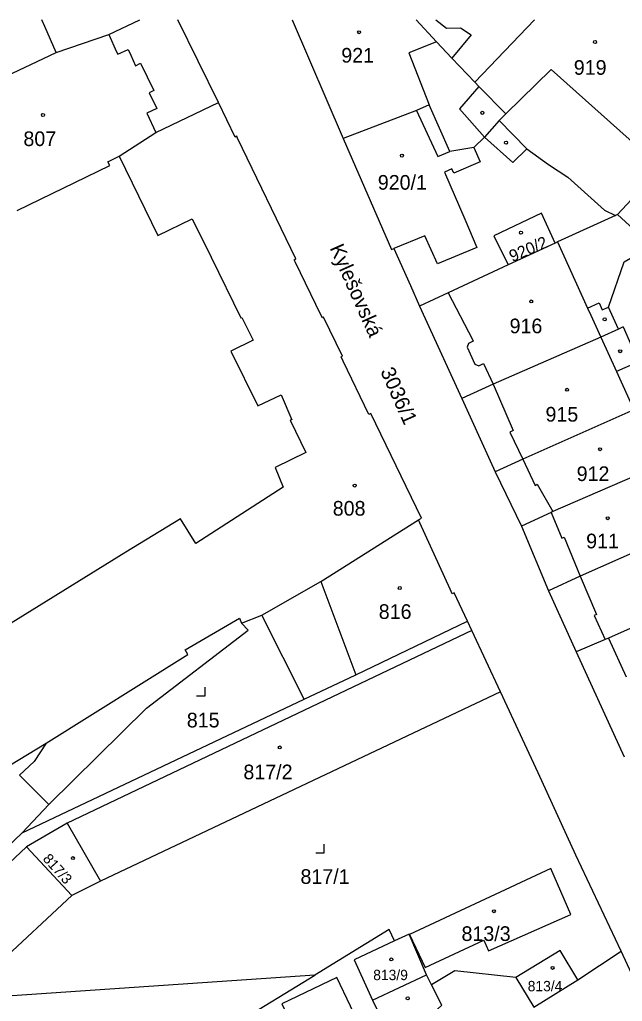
# Model space of a CAD drawing. Extents: x -496682 to -495907, y -1088575 to -1088018.
# Drawn here: x -496321.7 to -496251.9, y -1088133.3 to -1088019.5 of the extents above; entities that cross this region are included whole.
import ezdxf

# ---------------------------------------------------------------- set-up
doc = ezdxf.new("R2010")
doc.units = 0
for name, color, linetype in [('Hranice parcel', 7, 'Continuous'), ('Parcelní čísla', 7, 'Continuous'), ('Pop  PČ popisy', 7, 'Continuous'), ('Vnitřní kresba', 7, 'Continuous'), ('Značky budov', 7, 'Continuous'), ('Značky kultur', 7, 'Continuous')]:
    doc.layers.add(name, color=color, linetype=linetype)

msp = doc.modelspace()

# ---------------------------------------------------------------- linework, layer by layer
at = {"layer": 'Hranice parcel'}
for p, q in [((-496298.65, -1088029.08), (-496303.35, -1088019.49)), ((-496290.12, -1088019.49), (-496284.21, -1088033.27)), ((-496268.93, -1088026.74), (-496262.02, -1088019.49)), ((-496252.41, -1088042.06), (-496252.65, -1088042.17)), ((-496259.65, -1088045.38), (-496265.09, -1088047.92)), ((-496275.35, -1088052.7), (-496270.45, -1088063.42)), ((-496251.78, -1088055.1), (-496252.31, -1088055.35)), ((-496270.45, -1088063.42), (-496266.61, -1088071.89)), ((-496266.61, -1088071.89), (-496263.53, -1088078.19)), ((-496263.53, -1088078.19), (-496260.43, -1088085.68)), ((-496260.43, -1088085.68), (-496257.2, -1088092.78)), ((-496288.72, -1088098.27), (-496293.61, -1088088.52)), ((-496269.29, -1088090.31), (-496269.79, -1088089.23)), ((-496269.29, -1088090.31), (-496316.2, -1088112.62)), ((-496265.99, -1088097.42), (-496269.29, -1088090.31)), ((-496257.2, -1088092.78), (-496251.66, -1088104.94)), ((-496265.99, -1088097.42), (-496312.31, -1088119.35)), ((-496321.41, -1088113.75), (-496288.72, -1088098.27)), ((-496321.41, -1088113.75), (-496318.3, -1088110.48)), ((-496316.2, -1088112.62), (-496320.9, -1088115.37)), ((-496316.2, -1088112.62), (-496312.31, -1088119.35)), ((-496373.06, -1088163.12), (-496321.41, -1088113.75)), ((-496320.9, -1088115.37), (-496333.69, -1088127.43)), ((-496315.65, -1088120.99), (-496320.9, -1088115.37)), ((-496312.31, -1088119.35), (-496315.65, -1088120.99)), ((-496328.55, -1088133.03), (-496315.65, -1088120.99)), ((-496257, -1088130.8), (-496251.99, -1088127.48)), ((-496247.14, -1088138.02), (-496251.99, -1088127.48)), ((-496287.5, -1088130.23), (-496328.55, -1088133.03)), ((-496299.6, -1088137.62), (-496287.5, -1088130.23)), ((-496280.81, -1088133.14), (-496274.56, -1088130.21)), ((-496273.98, -1088131.36), (-496274.56, -1088130.21)), ((-496264.2, -1088130.52), (-496262.1, -1088133.95)), ((-496262.1, -1088133.95), (-496257, -1088130.8))]:
    msp.add_line(p, q, dxfattribs=at)
for points in [[(-496324.74, -1088026.75), (-496317.45, -1088023.28), (-496311.34, -1088021.2), (-496307.78, -1088019.49)], [(-496275.76, -1088019.49), (-496273.38, -1088022.04), (-496271.62, -1088023.96), (-496268.93, -1088026.74)], [(-496268.93, -1088026.74), (-496268.47, -1088027.22), (-496265.37, -1088030.41), (-496266.13, -1088031.18)], [(-496238.61, -1088027.35), (-496247.36, -1088036.67), (-496247.58, -1088036.9), (-496252.41, -1088042.06)], [(-496310.17, -1088035.32), (-496305.9, -1088032.56), (-496298.65, -1088029.08)], [(-496275.49, -1088077.48), (-496275.13, -1088077.26), (-496281.01, -1088065.15), (-496281.24, -1088065.26), (-496284.2, -1088059.06), (-496284.42, -1088058.56), (-496284.28, -1088058.49), (-496286.47, -1088053.98), (-496286.61, -1088054.04), (-496286.78, -1088053.72), (-496289.73, -1088047.63), (-496289.89, -1088047.33), (-496289.67, -1088047.22), (-496296.43, -1088033.23), (-496296.51, -1088033), (-496296.71, -1088033.1), (-496298.65, -1088029.08)], [(-496269.07, -1088034.31), (-496271.86, -1088034.77), (-496274.23, -1088029.37), (-496275.7, -1088030), (-496284.21, -1088033.27)], [(-496266.13, -1088031.18), (-496267.84, -1088033.11), (-496269.07, -1088034.31)], [(-496266.13, -1088031.18), (-496262.94, -1088034.46), (-496260.4, -1088036.29)], [(-496284.21, -1088033.27), (-496278.6, -1088046.13), (-496278.35, -1088046.03)], [(-496310.17, -1088035.32), (-496305.66, -1088044.52), (-496301.69, -1088042.58), (-496299.5, -1088047.02), (-496296.07, -1088054.07), (-496295.93, -1088054), (-496294.63, -1088056.63), (-496297.22, -1088057.91), (-496294.11, -1088064.26), (-496291.39, -1088062.99), (-496290.17, -1088065.87), (-496290.33, -1088065.93), (-496288.52, -1088069.67), (-496292.07, -1088071.39), (-496291.14, -1088073.66), (-496301.28, -1088080.22), (-496303.06, -1088077.33), (-496309.39, -1088081.23), (-496325.96, -1088091.45)], [(-496321.98, -1088041.61), (-496311.24, -1088036.41), (-496311.47, -1088035.95), (-496310.17, -1088035.32)], [(-496260.4, -1088036.29), (-496258.16, -1088037.74), (-496253.92, -1088041.57), (-496252.65, -1088042.17)], [(-496259.65, -1088045.38), (-496261.22, -1088041.9), (-496266.73, -1088044.55), (-496265.09, -1088047.92)], [(-496252.65, -1088042.17), (-496259.37, -1088045.25), (-496259.65, -1088045.38)], [(-496248.45, -1088045.69), (-496249.17, -1088045.03), (-496252.41, -1088042.06)], [(-496252.31, -1088055.35), (-496253.46, -1088052.82), (-496251.65, -1088047.57), (-496248.45, -1088045.69)], [(-496278.35, -1088046.03), (-496276.42, -1088050.3), (-496275.35, -1088052.7)], [(-496265.09, -1088047.92), (-496272.05, -1088051.15), (-496275.35, -1088052.7)], [(-496252.31, -1088055.35), (-496254.35, -1088056.3), (-496266.82, -1088061.74), (-496270.45, -1088063.42)], [(-496251.78, -1088055.1), (-496249.99, -1088059.14), (-496252.53, -1088060.29), (-496250.53, -1088064.7)], [(-496250.53, -1088064.7), (-496263.4, -1088070.45), (-496266.61, -1088071.89)], [(-496239.62, -1088065.03), (-496245.81, -1088070.34), (-496246.43, -1088070.68), (-496259.9, -1088076.48), (-496260.11, -1088076.62), (-496263.53, -1088078.19)], [(-496236.01, -1088072.37), (-496242.26, -1088077.59), (-496256.74, -1088083.98), (-496260.43, -1088085.68)], [(-496293.61, -1088088.52), (-496286.81, -1088084.63), (-496275.49, -1088077.48)], [(-496269.79, -1088089.23), (-496271.33, -1088085.91), (-496271.56, -1088086.03), (-496271.79, -1088085.51), (-496275.33, -1088077.82), (-496275.49, -1088077.48)], [(-496233.51, -1088080.25), (-496239.01, -1088084.74), (-496243.07, -1088086.55), (-496253.46, -1088091.18), (-496253.83, -1088091.34), (-496257.2, -1088092.78)], [(-496318.3, -1088110.48), (-496307.01, -1088099.28), (-496295.23, -1088090.25), (-496295.99, -1088089.43), (-496293.61, -1088088.52)], [(-496288.72, -1088098.27), (-496282.72, -1088095.43), (-496269.79, -1088089.23)], [(-496251.99, -1088127.48), (-496257.26, -1088116.34), (-496261.61, -1088106.78), (-496265.99, -1088097.42)], [(-496328.2, -1088109.13), (-496318.63, -1088103.36), (-496319.99, -1088105.46), (-496321.7, -1088107.07), (-496318.3, -1088110.48)], [(-496257.82, -1088123.22), (-496260.16, -1088117.88), (-496276.5, -1088125.53), (-496274.71, -1088129.36), (-496267.9, -1088126.18), (-496267.36, -1088127.41), (-496257.82, -1088123.22)], [(-496278.24, -1088126.28), (-496278.87, -1088124.96), (-496287.5, -1088130.23)], [(-496274.56, -1088130.21), (-496276.55, -1088125.49), (-496278.24, -1088126.28)], [(-496278.24, -1088126.28), (-496282.93, -1088128.45), (-496280.81, -1088133.14)], [(-496257, -1088130.8), (-496259.07, -1088127.4), (-496264.2, -1088130.52)], [(-496264.2, -1088130.52), (-496271.27, -1088129.74), (-496273.98, -1088131.36)], [(-496284.92, -1088130.53), (-496291.31, -1088133.56), (-496286.59, -1088143.52), (-496280.17, -1088140.48), (-496284.92, -1088130.53)], [(-496280.81, -1088133.14), (-496279.08, -1088136.73), (-496280.02, -1088137.23), (-496278.91, -1088139.32), (-496272.78, -1088133.72), (-496273.98, -1088131.36)]]:
    msp.add_lwpolyline(points, dxfattribs=at)
at = {"layer": 'Vnitřní kresba'}
for p, q in [((-496318.78, -1088020.28), (-496319.13, -1088019.49)), ((-496273.46, -1088019.49), (-496272.22, -1088020.47)), ((-496317.45, -1088023.28), (-496318.78, -1088020.28)), ((-496272.22, -1088020.47), (-496270.61, -1088020.44)), ((-496270.61, -1088020.44), (-496269.37, -1088021.26)), ((-496311.34, -1088021.2), (-496310.45, -1088023.2)), ((-496269.37, -1088021.26), (-496271.62, -1088023.96)), ((-496310.33, -1088023.47), (-496309.11, -1088022.93)), ((-496309.11, -1088022.93), (-496308.79, -1088023.6)), ((-496273.38, -1088022.04), (-496276.59, -1088023.33)), ((-496310.45, -1088023.2), (-496310.33, -1088023.47)), ((-496308.79, -1088023.6), (-496308.26, -1088024.86)), ((-496276.59, -1088023.33), (-496274.23, -1088029.37)), ((-496308.26, -1088024.86), (-496307.69, -1088024.52)), ((-496307.69, -1088024.52), (-496306.13, -1088027.69)), ((-496265.37, -1088030.41), (-496260.12, -1088025.28)), ((-496260.12, -1088025.28), (-496247.36, -1088036.67)), ((-496306.13, -1088027.69), (-496306.7, -1088027.99)), ((-496268.47, -1088027.22), (-496270.71, -1088029.82)), ((-496306.7, -1088027.99), (-496305.78, -1088029.78)), ((-496305.78, -1088029.78), (-496306.96, -1088030.34)), ((-496270.71, -1088029.82), (-496267.84, -1088033.11)), ((-496306.96, -1088030.34), (-496305.9, -1088032.56)), ((-496275.7, -1088030), (-496273.23, -1088035.35)), ((-496267.84, -1088033.11), (-496264.55, -1088036.03)), ((-496269.07, -1088034.31), (-496268.35, -1088035.97)), ((-496264.55, -1088036.03), (-496262.94, -1088034.46)), ((-496273.23, -1088035.35), (-496271.86, -1088034.77)), ((-496271.61, -1088036.79), (-496272.46, -1088037.16)), ((-496271.4, -1088037.27), (-496271.61, -1088036.79)), ((-496268.35, -1088035.97), (-496271.4, -1088037.27)), ((-496272.46, -1088037.16), (-496270.12, -1088042.62)), ((-496270.12, -1088042.62), (-496268.72, -1088045.9)), ((-496274.74, -1088044.56), (-496278.35, -1088046.03)), ((-496273.29, -1088047.81), (-496274.74, -1088044.56)), ((-496268.72, -1088045.9), (-496273.29, -1088047.81)), ((-496259.37, -1088045.25), (-496255.88, -1088052.93)), ((-496272.05, -1088051.15), (-496269.23, -1088056.55)), ((-496255.88, -1088052.93), (-496254.55, -1088052.32)), ((-496254.55, -1088052.32), (-496254.18, -1088053.14)), ((-496255.88, -1088052.93), (-496255.51, -1088053.75)), ((-496255.51, -1088053.75), (-496254.35, -1088056.3)), ((-496254.18, -1088053.14), (-496253.46, -1088052.82)), ((-496269.69, -1088057.04), (-496269.85, -1088057.45)), ((-496269.13, -1088056.74), (-496269.69, -1088057.04)), ((-496269.23, -1088056.55), (-496269.13, -1088056.74)), ((-496254.35, -1088056.3), (-496252.53, -1088060.29)), ((-496269.85, -1088057.45), (-496268.94, -1088059.43)), ((-496268.94, -1088059.43), (-496268.5, -1088059.6)), ((-496268.5, -1088059.6), (-496267.96, -1088059.33)), ((-496267.96, -1088059.33), (-496266.82, -1088061.74)), ((-496266.82, -1088061.74), (-496264.49, -1088067.11)), ((-496264.49, -1088067.11), (-496264.89, -1088067.29)), ((-496264.89, -1088067.29), (-496263.4, -1088070.45)), ((-496263.4, -1088070.45), (-496261.96, -1088073.47)), ((-496261.96, -1088073.47), (-496261.71, -1088073.32)), ((-496261.71, -1088073.32), (-496259.9, -1088076.48)), ((-496260.11, -1088076.62), (-496258.88, -1088079.59)), ((-496258.88, -1088079.59), (-496258.6, -1088079.47)), ((-496258.6, -1088079.47), (-496256.74, -1088083.98)), ((-496256.74, -1088083.98), (-496254.87, -1088088.42)), ((-496286.81, -1088084.63), (-496282.72, -1088095.43)), ((-496302.53, -1088092.55), (-496296.21, -1088088.86)), ((-496296.21, -1088088.86), (-496295.99, -1088089.43)), ((-496254.87, -1088088.42), (-496255.14, -1088088.54)), ((-496255.14, -1088088.54), (-496253.83, -1088091.34)), ((-496253.46, -1088091.18), (-496251.4, -1088095.68)), ((-496302.21, -1088093.07), (-496302.53, -1088092.55)), ((-496318.63, -1088103.36), (-496302.21, -1088093.07))]:
    msp.add_line(p, q, dxfattribs=at)
at = {"layer": 'Značky budov'}
for centre in [(-496282.36, -1088020.94), (-496255.02, -1088022.08), (-496318.99, -1088030.54), (-496268.08, -1088030.29), (-496265.33, -1088033.75), (-496277.4, -1088035.25), (-496263.6, -1088044.18), (-496262.42, -1088052.15), (-496253.9, -1088054.23), (-496252.11, -1088057.92), (-496258.26, -1088062.39), (-496254.43, -1088069.28), (-496282.87, -1088073.49), (-496253.55, -1088077.28), (-496277.64, -1088085.37), (-496291.55, -1088103.85), (-496315.52, -1088116.68), (-496266.74, -1088122.83), (-496278.63, -1088128.42), (-496259.94, -1088129.4), (-496276.73, -1088132.93)]:
    msp.add_circle(centre, 0.175, dxfattribs=at)
at = {"layer": 'Značky kultur'}
for p, q in [((-496300.19, -1088097.85), (-496300.19, -1088096.85)), ((-496301.19, -1088097.85), (-496300.19, -1088097.85)), ((-496286.39, -1088116.05), (-496286.39, -1088115.05)), ((-496287.39, -1088116.05), (-496286.39, -1088116.05))]:
    msp.add_line(p, q, dxfattribs=at)

# ---------------------------------------------------------------- texts
at = {"layer": 'Parcelní čísla'}
for s, height, p in [('921', 1.7, (-496284.42, -1088024.47)), ('919', 1.7, (-496257.48, -1088025.88)), ('807', 1.7, (-496321.25, -1088034.14)), ('920/1', 1.7, (-496280.19, -1088039.2)), ('916', 1.7, (-496264.92, -1088055.84)), ('915', 1.7, (-496260.76, -1088066.08)), ('912', 1.7, (-496257.15, -1088072.97)), ('808', 1.7, (-496285.41, -1088076.98)), ('911', 1.7, (-496256.05, -1088080.77)), ('816', 1.7, (-496280.08, -1088088.95)), ('815', 1.7, (-496302.32, -1088101.53)), ('817/2', 1.7, (-496295.76, -1088107.54)), ('817/1', 1.7, (-496289.15, -1088119.66)), ('813/3', 1.7, (-496270.49, -1088126.28)), ('813/9', 1.2, (-496280.72, -1088130.82)), ('813/4', 1.2, (-496262.82, -1088132.11))]:
    msp.add_text(s, height=height, dxfattribs=at).set_placement(p)
for s, height, rotation, p in [('920/2', 1.378, 23, (-496264.61, -1088047.61)), ('3036/1', 1.7, 294, (-496279.93, -1088060.24)), ('817/3', 1.2, 312, (-496319.08, -1088116.82))]:
    msp.add_text(s, height=height, rotation=rotation, dxfattribs=at).set_placement(p)
at = {"layer": 'Pop  PČ popisy'}
msp.add_text('Kylešovská', height=1.7, rotation=294, dxfattribs=at).set_placement((-496285.8, -1088045.95))

doc.saveas('drawing.dxf')
